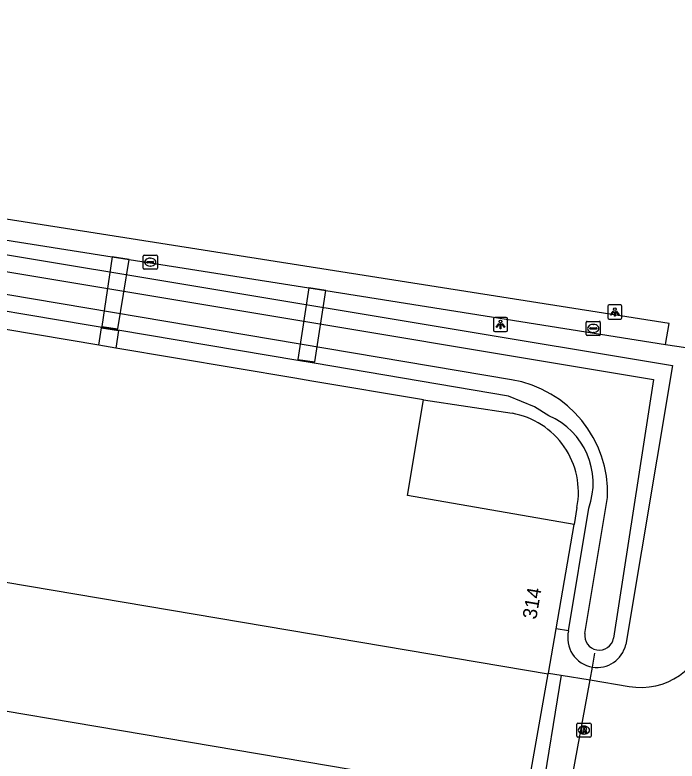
# Model space of a CAD drawing. Extents: x 161094 to 161705, y 379509 to 380907.
# Drawn here: x 161482.5 to 161529.5, y 379919.3 to 379972.2 of the extents above; entities that cross this region are included whole.
import ezdxf

# ---------------------------------------------------------------- set-up
doc = ezdxf.new("R2010")
doc.units = 0
for name, color, linetype in [('IMGEO_Dek', 7, 'Continuous'), ('IMGEO_Duiker', 7, 'Continuous'), ('IMGEO_Groenvoorziening', 7, 'Continuous'), ('IMGEO_Lichtpunt', 7, 'Continuous'), ('IMGEO_Pand', 7, 'Continuous'), ('IMGEO_Pand_nummerreeks', 7, 'Continuous'), ('IMGEO_Rijbaan_lokaal_open', 7, 'Continuous'), ('IMGEO_Rioolput', 7, 'Continuous'), ('IMGEO_Voetpad_gesloten', 7, 'Continuous'), ('IMGEO_Voetpad_open', 7, 'Continuous'), ('IMGEO_Waterleidingput', 7, 'Continuous'), ('IMGEO_Waterloop', 7, 'Continuous')]:
    doc.layers.add(name, color=color, linetype=linetype)

msp = doc.modelspace()

# ---------------------------------------------------------------- linework, layer by layer
at = {"layer": 'IMGEO_Dek'}
for points in [[(161489.414, 379955.043), (161488.666, 379950.105), (161489.811, 379949.928), (161490.618, 379954.853)], [(161503.353, 379952.839), (161502.581, 379947.775), (161503.765, 379947.6), (161504.564, 379952.647)]]:
    msp.add_lwpolyline(points, close=True, dxfattribs=at)
at = {"layer": 'IMGEO_Duiker'}
msp.add_lwpolyline([(161521.213, 379913.764), (161521.359, 379914.557), (161521.659, 379916.19), (161523.289, 379925.051), (161523.456, 379925.959), (161523.636, 379926.94)], dxfattribs=at)
at = {"layer": 'IMGEO_Groenvoorziening'}
for points in [[(161463.491, 379958.267), (161529.143, 379947.348), (161525.825, 379927.554)], [(161528.642, 379948.839), (161534.566, 379947.954)]]:
    msp.add_lwpolyline(points, dxfattribs=at)
for centre, radius, start, end in [((161523.791, 379928.018), 2.086, 165.5898, 260.7481), ((161523.788, 379928.023), 2.091, 260.8708, 347.0324)]:
    msp.add_arc(centre, radius, start, end, dxfattribs=at)
at = {"layer": 'IMGEO_Lichtpunt'}
for p, q in [((161524.545, 379951.534), (161524.545, 379950.727)), ((161524.545, 379951.534), (161524.545, 379950.727)), ((161525.447, 379951.629), (161524.639, 379951.629)), ((161525.447, 379951.629), (161524.639, 379951.629)), ((161525.541, 379950.727), (161525.541, 379951.534)), ((161525.541, 379950.727), (161525.541, 379951.534)), ((161516.443, 379950.651), (161516.443, 379949.844)), ((161516.443, 379950.651), (161516.443, 379949.844)), ((161517.345, 379950.746), (161516.537, 379950.746)), ((161517.345, 379950.746), (161516.537, 379950.746)), ((161517.439, 379949.844), (161517.439, 379950.651)), ((161517.439, 379949.844), (161517.439, 379950.651)), ((161524.639, 379950.633), (161525.447, 379950.633)), ((161524.639, 379950.633), (161525.447, 379950.633)), ((161516.537, 379949.75), (161517.345, 379949.75)), ((161516.537, 379949.75), (161517.345, 379949.75))]:
    msp.add_line(p, q, dxfattribs=at)
for points in [[(161524.919, 379951.198), (161524.958, 379951.17), (161524.77, 379950.908), (161524.732, 379950.935), (161524.919, 379951.198)], [(161525.021, 379951.15), (161525.068, 379951.15), (161525.068, 379950.828), (161525.021, 379950.828), (161525.021, 379951.15)], [(161525.131, 379951.17), (161525.169, 379951.197), (161525.356, 379950.935), (161525.317, 379950.907), (161525.131, 379951.17)], [(161516.817, 379950.315), (161516.856, 379950.287), (161516.668, 379950.025), (161516.63, 379950.052), (161516.817, 379950.315)], [(161517.029, 379950.287), (161517.067, 379950.314), (161517.254, 379950.052), (161517.215, 379950.024), (161517.029, 379950.287)], [(161516.919, 379950.267), (161516.966, 379950.267), (161516.966, 379949.945), (161516.919, 379949.945), (161516.919, 379950.267)]]:
    msp.add_lwpolyline(points, dxfattribs=at)
for centre in [(161525.044, 379951.332), (161516.942, 379950.449)]:
    msp.add_circle(centre, 0.0994, dxfattribs=at)
for centre, start, end in [((161524.639, 379951.534), 90, 180), ((161524.639, 379951.534), 90, 180), ((161525.447, 379951.534), 0, 90), ((161525.447, 379951.534), 0, 90), ((161516.537, 379950.651), 90, 180), ((161516.537, 379950.651), 90, 180), ((161517.345, 379950.651), 0, 90), ((161517.345, 379950.651), 0, 90), ((161524.639, 379950.727), 180, 270), ((161524.639, 379950.727), 180, 270), ((161525.447, 379950.727), 270, 0), ((161525.447, 379950.727), 270, 360), ((161516.537, 379949.844), 180, 270), ((161516.537, 379949.844), 180, 270), ((161517.345, 379949.844), 270, 0), ((161517.345, 379949.844), 270, 360)]:
    msp.add_arc(centre, 0.0946, start, end, dxfattribs=at)
at = {"layer": 'IMGEO_Pand'}
for points in [[(161488.466, 379948.778), (161466.406, 379952.494), (161461.941, 379953.246)], [(161489.675, 379948.574), (161488.466, 379948.778)], [(161511.482, 379944.901), (161503.555, 379946.236), (161502.356, 379946.438), (161489.675, 379948.574)], [(161522.174, 379936.061), (161510.34, 379938.122), (161511.482, 379944.901)], [(161448.37, 379928.041), (161449.951, 379937.373), (161520.33, 379925.471)], [(161520.887, 379928.67), (161522.174, 379936.061)], [(161520.341, 379925.533), (161520.887, 379928.67)], [(161514.139, 379917.319), (161511.311, 379917.848), (161457.045, 379927.006)], [(161520.33, 379925.471), (161520.341, 379925.533)]]:
    msp.add_lwpolyline(points, dxfattribs=at)
at = {"layer": 'IMGEO_Rijbaan_lokaal_open'}
for points in [[(161518.754, 379916.647), (161520.33, 379925.471)], [(161520.341, 379925.533), (161521.239, 379925.396)], [(161521.239, 379925.396), (161519.795, 379916.496)], [(161521.239, 379925.396), (161523.289, 379925.051), (161526.064, 379924.584)]]:
    msp.add_lwpolyline(points, dxfattribs=at)
msp.add_arc((161526.889, 379929.322), 4.81, 260.1205, 349.2097, dxfattribs=at)
at = {"layer": 'IMGEO_Rioolput'}
for p, q in [((161522.358, 379921.063), (161522.358, 379921.915)), ((161522.433, 379921.989), (161523.285, 379921.989)), ((161522.846, 379921.769), (161522.871, 379921.769)), ((161523.359, 379921.915), (161523.359, 379921.063)), ((161522.869, 379921.209), (161522.844, 379921.209)), ((161523.285, 379920.989), (161522.433, 379920.989))]:
    msp.add_line(p, q, dxfattribs=at)
for points in [[(161522.358, 379921.063), (161522.358, 379921.915)], [(161522.433, 379921.989), (161523.285, 379921.989)], [(161523.359, 379921.915), (161523.359, 379921.063)], [(161522.947, 379921.687), (161522.695, 379921.689), (161522.695, 379921.289)], [(161522.695, 379921.289), (161522.819, 379921.289), (161522.819, 379921.451), (161522.83, 379921.451)], [(161522.873, 379921.608), (161522.819, 379921.608), (161522.819, 379921.527)], [(161522.819, 379921.527), (161522.871, 379921.527)], [(161522.877, 379921.422), (161522.948, 379921.289), (161523.088, 379921.289), (161523.023, 379921.415)], [(161523.285, 379920.989), (161522.433, 379920.989)]]:
    msp.add_lwpolyline(points, dxfattribs=at)
for centre, radius, start, end in [((161522.435, 379921.913), 0.0765, 91.552, 178.448), ((161522.435, 379921.913), 0.0765, 91.552, 178.448), ((161523.283, 379921.913), 0.0765, 1.552, 88.448), ((161523.283, 379921.913), 0.0765, 1.552, 88.448), ((161522.829, 379921.398), 0.0533, 26.0293, 88.6989), ((161522.855, 379921.716), 0.19, 274.7715, 282.9687), ((161522.879, 379921.512), 0.0964, 77.0061, 93.1865), ((161522.893, 379921.569), 0.0378, 276.6634, 79.6772), ((161522.946, 379921.577), 0.109, 350.3612, 89.416), ((161522.944, 379921.577), 0.112, 277.5842, 350.9817), ((161522.928, 379921.362), 0.108, 29.5134, 73.7905), ((161522.435, 379921.065), 0.0765, 181.552, 268.448), ((161522.435, 379921.065), 0.0765, 181.552, 268.448), ((161523.283, 379921.065), 0.0765, 271.552, 358.448), ((161523.283, 379921.065), 0.0765, 271.552, 358.448)]:
    msp.add_arc(centre, radius, start, end, dxfattribs=at)
for centre, major_axis, ratio, start_param, end_param in [((161522.845, 379921.489), (-0.387, 0.002), 0.722429, 4.712389, 7.853982), ((161522.87, 379921.489), (-0.39, 0.002), 0.717154, 1.570796, 4.712389)]:
    msp.add_ellipse(centre, major_axis=major_axis, ratio=ratio, start_param=start_param, end_param=end_param, dxfattribs=at)
at = {"layer": 'IMGEO_Voetpad_gesloten'}
for points in [[(161490.618, 379954.853), (161489.414, 379955.043), (161488.666, 379950.105), (161489.811, 379949.928), (161490.618, 379954.853)], [(161503.353, 379952.839), (161502.581, 379947.775), (161503.765, 379947.6), (161504.564, 379952.647), (161503.353, 379952.839)]]:
    msp.add_lwpolyline(points, dxfattribs=at)
at = {"layer": 'IMGEO_Voetpad_open'}
for points in [[(161528.642, 379948.839), (161528.895, 379950.307), (161460.249, 379961.111), (161468.78, 380015.282), (161469.34, 380019.004), (161469.797, 380021.965)], [(161458.131, 379954.643), (161460.184, 379954.317), (161461.018, 379959.534), (161489.414, 379955.043), (161490.618, 379954.853), (161503.353, 379952.839), (161504.564, 379952.647), (161528.642, 379948.839)], [(161520.366, 379943.774), (161519.362, 379944.405), (161517.519, 379945.175), (161503.732, 379947.499), (161502.561, 379947.696), (161462.164, 379954.505)], [(161488.466, 379948.778), (161488.65, 379950.013), (161489.852, 379949.809), (161489.675, 379948.574)], [(161511.482, 379944.901), (161517.757, 379943.954)], [(161521.771, 379928.537), (161523.199, 379937.227)], [(161522.363, 379937.271), (161522.174, 379936.061)], [(161521.771, 379928.537), (161520.887, 379928.67)]]:
    msp.add_lwpolyline(points, dxfattribs=at)
for centre, radius, start, end in [((161516.777, 379938.35), 5.689, 349.0692, 80.0809), ((161518.312, 379938.999), 5.198, 340.07, 66.7279)]:
    msp.add_arc(centre, radius, start, end, dxfattribs=at)
at = {"layer": 'IMGEO_Waterleidingput'}
for p, q in [((161491.608, 379954.24), (161491.608, 379955.092)), ((161491.683, 379955.166), (161492.535, 379955.166)), ((161492.609, 379955.092), (161492.609, 379954.24)), ((161491.867, 379954.66), (161491.867, 379954.672)), ((161492.305, 379954.623), (161491.907, 379954.623)), ((161491.91, 379954.709), (161492.308, 379954.709)), ((161492.096, 379954.946), (161492.121, 379954.946)), ((161492.351, 379954.672), (161492.351, 379954.66)), ((161492.535, 379954.166), (161491.683, 379954.166)), ((161492.119, 379954.386), (161492.094, 379954.386)), ((161523.018, 379949.543), (161523.018, 379950.395)), ((161523.093, 379950.469), (161523.945, 379950.469)), ((161524.019, 379950.395), (161524.019, 379949.543)), ((161523.277, 379949.963), (161523.277, 379949.975)), ((161523.715, 379949.926), (161523.317, 379949.926)), ((161523.32, 379950.012), (161523.718, 379950.012)), ((161523.506, 379950.249), (161523.531, 379950.249)), ((161523.761, 379949.975), (161523.761, 379949.963)), ((161523.945, 379949.469), (161523.093, 379949.469)), ((161523.529, 379949.689), (161523.504, 379949.689))]:
    msp.add_line(p, q, dxfattribs=at)
for points in [[(161491.608, 379954.24), (161491.608, 379955.092)], [(161491.683, 379955.166), (161492.535, 379955.166)], [(161492.609, 379955.092), (161492.609, 379954.24)], [(161492.535, 379954.166), (161491.683, 379954.166)], [(161523.018, 379949.543), (161523.018, 379950.395)], [(161523.093, 379950.469), (161523.945, 379950.469)], [(161524.019, 379950.395), (161524.019, 379949.543)], [(161523.945, 379949.469), (161523.093, 379949.469)]]:
    msp.add_lwpolyline(points, dxfattribs=at)
for centre, radius, start, end in [((161491.685, 379955.09), 0.0765, 91.552, 178.448), ((161491.685, 379955.09), 0.0765, 91.552, 178.448), ((161492.533, 379955.09), 0.0765, 1.552, 88.448), ((161492.533, 379955.09), 0.0765, 1.552, 88.448), ((161491.907, 379954.669), 0.0403, 85.8775, 175.7526), ((161491.904, 379954.659), 0.0366, 178.938, 274.7102), ((161492.308, 379954.666), 0.043, 264.8664, 352.4533), ((161492.312, 379954.671), 0.0386, 1.7309, 96.639), ((161491.685, 379954.242), 0.0765, 181.552, 268.448), ((161491.685, 379954.242), 0.0765, 181.552, 268.448), ((161492.533, 379954.242), 0.0765, 271.552, 358.448), ((161492.533, 379954.242), 0.0765, 271.552, 358.448), ((161523.095, 379950.393), 0.0765, 91.552, 178.448), ((161523.095, 379950.393), 0.0765, 91.552, 178.448), ((161523.943, 379950.393), 0.0765, 1.552, 88.448), ((161523.943, 379950.393), 0.0765, 1.552, 88.448), ((161523.317, 379949.972), 0.0403, 85.8775, 175.7526), ((161523.314, 379949.962), 0.0366, 178.938, 274.7102), ((161523.718, 379949.969), 0.043, 264.8664, 352.4533), ((161523.722, 379949.974), 0.0386, 1.7309, 96.639), ((161523.095, 379949.545), 0.0765, 181.552, 268.448), ((161523.095, 379949.545), 0.0765, 181.552, 268.448), ((161523.943, 379949.545), 0.0765, 271.552, 358.448), ((161523.943, 379949.545), 0.0765, 271.552, 358.448)]:
    msp.add_arc(centre, radius, start, end, dxfattribs=at)
for centre, major_axis, ratio, start_param, end_param in [((161492.095, 379954.666), (-0.387, 0.002), 0.722429, 4.712389, 7.853982), ((161492.12, 379954.666), (-0.39, 0.002), 0.717154, 1.570796, 4.712389), ((161523.505, 379949.969), (-0.387, 0.002), 0.722429, 4.712389, 7.853982), ((161523.53, 379949.969), (-0.39, 0.002), 0.717154, 1.570796, 4.712389)]:
    msp.add_ellipse(centre, major_axis=major_axis, ratio=ratio, start_param=start_param, end_param=end_param, dxfattribs=at)
at = {"layer": 'IMGEO_Waterloop'}
for points in [[(161463.297, 379957.103), (161527.787, 379946.344), (161524.955, 379928.002)], [(161517.714, 379946.329), (161463.068, 379955.539)], [(161522.925, 379928.347), (161524.531, 379937.976)]]:
    msp.add_lwpolyline(points, dxfattribs=at)
for centre, radius, start, end in [((161516.378, 379938.281), 8.158, 357.8596, 80.5771), ((161523.943, 379928.19), 1.03, 171.2351, 349.4743)]:
    msp.add_arc(centre, radius, start, end, dxfattribs=at)

# ---------------------------------------------------------------- texts
at = {"layer": 'IMGEO_Pand_nummerreeks'}
msp.add_text('314', height=1, rotation=80.1224, dxfattribs=at).set_placement((161519.475, 379929.301))

doc.saveas('drawing.dxf')
